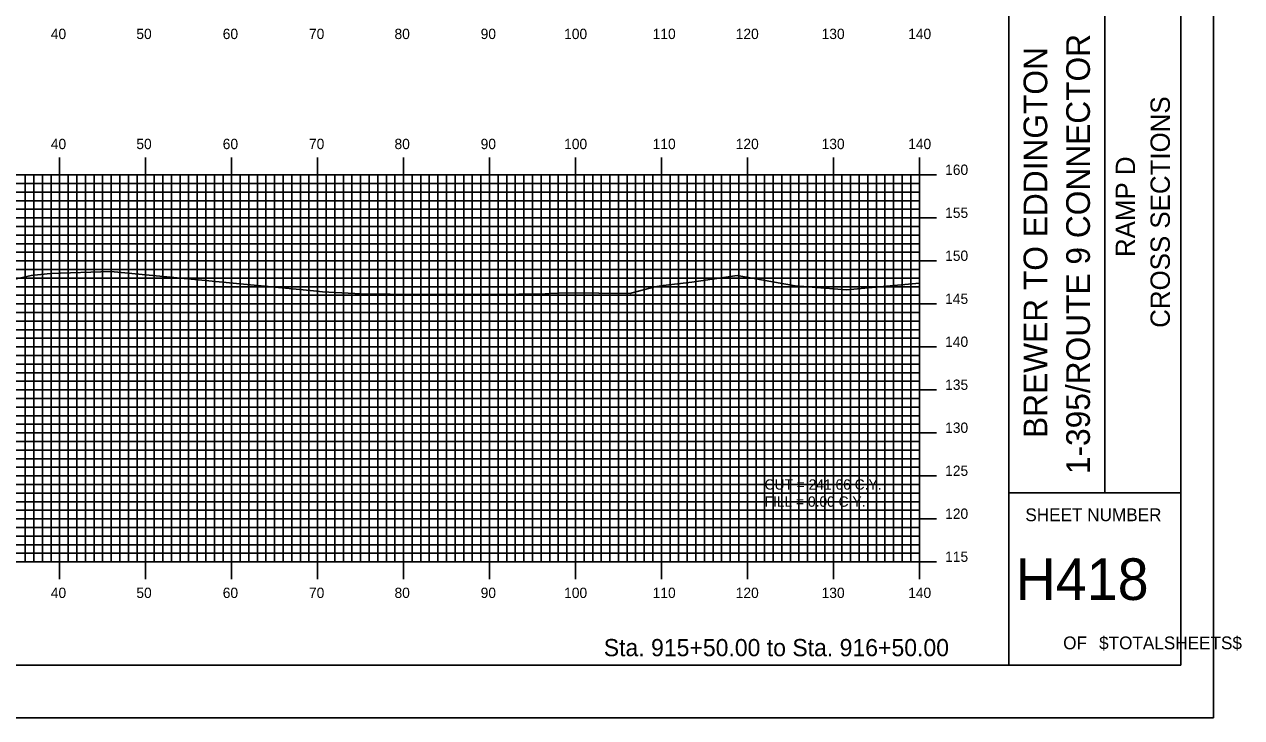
# Model space of a CAD drawing. Extents: x 861045 to 861388, y 364765 to 364985.
# Drawn here: x 861246.8 to 861388.4, y 364765.2 to 364845.8 of the extents above; entities that cross this region are included whole.
import ezdxf

# ---------------------------------------------------------------- set-up
doc = ezdxf.new("R2010")
doc.units = 0
for name, color, linetype in [('BORDER', 7, 'Continuous'), ('D_Text_Standard', 7, 'Continuous'), ('H_V ANNOTATION', 7, 'Continuous'), ('MAJOR', 7, 'Continuous'), ('MINOR', 7, 'Continuous'), ('PLOT BOUNDARY', 7, 'Continuous'), ('S_Roadway_Centerline', 7, 'Continuous')]:
    doc.layers.add(name, color=color, linetype=linetype)

msp = doc.modelspace()

# ---------------------------------------------------------------- linework, layer by layer
at = {"layer": 'BORDER'}
for p, q in [((861361.33, 364771.3), (861361.33, 364981.3)), ((861372.51, 364791.31), (861372.51, 364861.31)), ((861361.33, 364791.31), (861381.33, 364791.31))]:
    msp.add_line(p, q, dxfattribs=at)
msp.add_lwpolyline([(861061.33, 364771.3), (861381.33, 364771.3), (861381.33, 364981.3), (861061.33, 364981.3)], close=True, dxfattribs=at)
at = {"layer": 'MAJOR'}
for p, q in [((861250.93, 364830.31), (861250.93, 364828.3)), ((861260.93, 364830.31), (861260.93, 364828.3)), ((861270.93, 364830.31), (861270.93, 364828.3)), ((861280.93, 364830.31), (861280.93, 364828.3)), ((861290.93, 364830.31), (861290.93, 364828.3)), ((861300.93, 364830.31), (861300.93, 364828.3)), ((861310.93, 364830.31), (861310.93, 364828.3)), ((861320.93, 364830.31), (861320.93, 364828.3)), ((861330.93, 364830.31), (861330.93, 364828.3)), ((861340.93, 364830.31), (861340.93, 364828.3)), ((861350.93, 364830.31), (861350.93, 364828.3)), ((861070.93, 364828.3), (861350.93, 364828.3)), ((861070.93, 364828.3), (861350.93, 364828.3)), ((861250.93, 364783.3), (861250.93, 364828.3)), ((861260.93, 364783.3), (861260.93, 364828.3)), ((861270.93, 364783.3), (861270.93, 364828.3)), ((861280.93, 364783.3), (861280.93, 364828.3)), ((861290.93, 364783.3), (861290.93, 364828.3)), ((861300.93, 364783.3), (861300.93, 364828.3)), ((861310.93, 364783.3), (861310.93, 364828.3)), ((861320.93, 364783.3), (861320.93, 364828.3)), ((861330.93, 364783.3), (861330.93, 364828.3)), ((861340.93, 364783.3), (861340.93, 364828.3)), ((861352.93, 364828.3), (861348.92, 364828.3)), ((861350.93, 364783.3), (861350.93, 364828.3)), ((861350.93, 364783.3), (861350.93, 364828.3)), ((861070.93, 364823.3), (861350.93, 364823.3)), ((861352.93, 364823.3), (861348.92, 364823.3)), ((861070.93, 364818.3), (861350.93, 364818.3)), ((861352.93, 364818.3), (861348.92, 364818.3)), ((861070.93, 364813.3), (861350.93, 364813.3)), ((861352.93, 364813.3), (861348.92, 364813.3)), ((861070.93, 364808.3), (861350.93, 364808.3)), ((861352.93, 364808.3), (861348.92, 364808.3)), ((861070.93, 364803.3), (861350.93, 364803.3)), ((861352.93, 364803.3), (861348.92, 364803.3)), ((861070.93, 364798.3), (861350.93, 364798.3)), ((861352.93, 364798.3), (861348.92, 364798.3)), ((861070.93, 364793.3), (861350.93, 364793.3)), ((861352.93, 364793.3), (861348.92, 364793.3)), ((861070.93, 364788.3), (861350.93, 364788.3)), ((861352.93, 364788.3), (861348.92, 364788.3)), ((861070.93, 364783.3), (861350.93, 364783.3)), ((861070.93, 364783.3), (861350.93, 364783.3)), ((861250.93, 364781.3), (861250.93, 364783.3)), ((861260.93, 364781.3), (861260.93, 364783.3)), ((861270.93, 364781.3), (861270.93, 364783.3)), ((861280.93, 364781.3), (861280.93, 364783.3)), ((861290.93, 364781.3), (861290.93, 364783.3)), ((861300.93, 364781.3), (861300.93, 364783.3)), ((861310.93, 364781.3), (861310.93, 364783.3)), ((861320.93, 364781.3), (861320.93, 364783.3)), ((861330.93, 364781.3), (861330.93, 364783.3)), ((861340.93, 364781.3), (861340.93, 364783.3)), ((861352.93, 364783.3), (861348.92, 364783.3)), ((861350.93, 364781.3), (861350.93, 364783.3))]:
    msp.add_line(p, q, dxfattribs=at)
at = {"layer": 'MINOR'}
for p, q in [((861246.93, 364783.3), (861246.93, 364828.3)), ((861247.93, 364783.3), (861247.93, 364828.3)), ((861248.93, 364783.3), (861248.93, 364828.3)), ((861249.93, 364783.3), (861249.93, 364828.3)), ((861251.93, 364783.3), (861251.93, 364828.3)), ((861252.93, 364783.3), (861252.93, 364828.3)), ((861253.93, 364783.3), (861253.93, 364828.3)), ((861254.93, 364783.3), (861254.93, 364828.3)), ((861255.93, 364783.3), (861255.93, 364828.3)), ((861256.93, 364783.3), (861256.93, 364828.3)), ((861257.93, 364783.3), (861257.93, 364828.3)), ((861258.93, 364783.3), (861258.93, 364828.3)), ((861259.93, 364783.3), (861259.93, 364828.3)), ((861261.93, 364783.3), (861261.93, 364828.3)), ((861262.93, 364783.3), (861262.93, 364828.3)), ((861263.93, 364783.3), (861263.93, 364828.3)), ((861264.93, 364783.3), (861264.93, 364828.3)), ((861265.93, 364783.3), (861265.93, 364828.3)), ((861266.93, 364783.3), (861266.93, 364828.3)), ((861267.93, 364783.3), (861267.93, 364828.3)), ((861268.93, 364783.3), (861268.93, 364828.3)), ((861269.93, 364783.3), (861269.93, 364828.3)), ((861271.93, 364783.3), (861271.93, 364828.3)), ((861272.93, 364783.3), (861272.93, 364828.3)), ((861273.93, 364783.3), (861273.93, 364828.3)), ((861274.93, 364783.3), (861274.93, 364828.3)), ((861275.93, 364783.3), (861275.93, 364828.3)), ((861276.93, 364783.3), (861276.93, 364828.3)), ((861277.93, 364783.3), (861277.93, 364828.3)), ((861278.93, 364783.3), (861278.93, 364828.3)), ((861279.93, 364783.3), (861279.93, 364828.3)), ((861281.93, 364783.3), (861281.93, 364828.3)), ((861282.93, 364783.3), (861282.93, 364828.3)), ((861283.93, 364783.3), (861283.93, 364828.3)), ((861284.93, 364783.3), (861284.93, 364828.3)), ((861285.93, 364783.3), (861285.93, 364828.3)), ((861286.93, 364783.3), (861286.93, 364828.3)), ((861287.93, 364783.3), (861287.93, 364828.3)), ((861288.93, 364783.3), (861288.93, 364828.3)), ((861289.93, 364783.3), (861289.93, 364828.3)), ((861291.93, 364783.3), (861291.93, 364828.3)), ((861292.93, 364783.3), (861292.93, 364828.3)), ((861293.93, 364783.3), (861293.93, 364828.3)), ((861294.93, 364783.3), (861294.93, 364828.3)), ((861295.93, 364783.3), (861295.93, 364828.3)), ((861296.93, 364783.3), (861296.93, 364828.3)), ((861297.93, 364783.3), (861297.93, 364828.3)), ((861298.93, 364783.3), (861298.93, 364828.3)), ((861299.93, 364783.3), (861299.93, 364828.3)), ((861301.93, 364783.3), (861301.93, 364828.3)), ((861302.93, 364783.3), (861302.93, 364828.3)), ((861303.93, 364783.3), (861303.93, 364828.3)), ((861304.93, 364783.3), (861304.93, 364828.3)), ((861305.93, 364783.3), (861305.93, 364828.3)), ((861306.93, 364783.3), (861306.93, 364828.3)), ((861307.93, 364783.3), (861307.93, 364828.3)), ((861308.93, 364783.3), (861308.93, 364828.3)), ((861309.93, 364783.3), (861309.93, 364828.3)), ((861311.93, 364783.3), (861311.93, 364828.3)), ((861312.93, 364783.3), (861312.93, 364828.3)), ((861313.93, 364783.3), (861313.93, 364828.3)), ((861314.93, 364783.3), (861314.93, 364828.3)), ((861315.93, 364783.3), (861315.93, 364828.3)), ((861316.93, 364783.3), (861316.93, 364828.3)), ((861317.93, 364783.3), (861317.93, 364828.3)), ((861318.93, 364783.3), (861318.93, 364828.3)), ((861319.93, 364783.3), (861319.93, 364828.3)), ((861321.93, 364783.3), (861321.93, 364828.3)), ((861322.93, 364783.3), (861322.93, 364828.3)), ((861323.93, 364783.3), (861323.93, 364828.3)), ((861324.93, 364783.3), (861324.93, 364828.3)), ((861325.93, 364783.3), (861325.93, 364828.3)), ((861326.93, 364783.3), (861326.93, 364828.3)), ((861327.93, 364783.3), (861327.93, 364828.3)), ((861328.93, 364783.3), (861328.93, 364828.3)), ((861329.93, 364783.3), (861329.93, 364828.3)), ((861331.93, 364783.3), (861331.93, 364828.3)), ((861332.93, 364783.3), (861332.93, 364828.3)), ((861333.93, 364783.3), (861333.93, 364828.3)), ((861334.93, 364783.3), (861334.93, 364828.3)), ((861335.93, 364783.3), (861335.93, 364828.3)), ((861336.93, 364783.3), (861336.93, 364828.3)), ((861337.93, 364783.3), (861337.93, 364828.3)), ((861338.93, 364783.3), (861338.93, 364828.3)), ((861339.93, 364783.3), (861339.93, 364828.3)), ((861341.93, 364783.3), (861341.93, 364828.3)), ((861342.93, 364783.3), (861342.93, 364828.3)), ((861343.93, 364783.3), (861343.93, 364828.3)), ((861344.93, 364783.3), (861344.93, 364828.3)), ((861345.93, 364783.3), (861345.93, 364828.3)), ((861346.93, 364783.3), (861346.93, 364828.3)), ((861347.93, 364783.3), (861347.93, 364828.3)), ((861348.93, 364783.3), (861348.93, 364828.3)), ((861349.93, 364783.3), (861349.93, 364828.3)), ((861070.93, 364827.3), (861350.93, 364827.3)), ((861350.93, 364827.3), (861348.92, 364827.3)), ((861070.93, 364826.3), (861350.93, 364826.3)), ((861350.93, 364826.3), (861348.92, 364826.3)), ((861070.93, 364825.3), (861350.93, 364825.3)), ((861070.93, 364824.3), (861350.93, 364824.3)), ((861350.93, 364825.3), (861348.92, 364825.3)), ((861350.93, 364824.3), (861348.92, 364824.3)), ((861070.93, 364822.3), (861350.93, 364822.3)), ((861070.93, 364821.3), (861350.93, 364821.3)), ((861350.93, 364822.3), (861348.92, 364822.3)), ((861350.93, 364821.3), (861348.92, 364821.3)), ((861070.93, 364820.3), (861350.93, 364820.3)), ((861350.93, 364820.3), (861348.92, 364820.3)), ((861070.93, 364819.3), (861350.93, 364819.3)), ((861350.93, 364819.3), (861348.92, 364819.3)), ((861070.93, 364817.3), (861350.93, 364817.3)), ((861350.93, 364817.3), (861348.92, 364817.3)), ((861070.93, 364816.3), (861350.93, 364816.3)), ((861350.93, 364816.3), (861348.92, 364816.3)), ((861070.93, 364815.3), (861350.93, 364815.3)), ((861070.93, 364814.3), (861350.93, 364814.3)), ((861350.93, 364815.3), (861348.92, 364815.3)), ((861350.93, 364814.3), (861348.92, 364814.3)), ((861070.93, 364812.3), (861350.93, 364812.3)), ((861070.93, 364811.3), (861350.93, 364811.3)), ((861350.93, 364812.3), (861348.92, 364812.3)), ((861350.93, 364811.3), (861348.92, 364811.3)), ((861070.93, 364810.3), (861350.93, 364810.3)), ((861350.93, 364810.3), (861348.92, 364810.3)), ((861070.93, 364809.3), (861350.93, 364809.3)), ((861350.93, 364809.3), (861348.92, 364809.3)), ((861070.93, 364807.3), (861350.93, 364807.3)), ((861350.93, 364807.3), (861348.92, 364807.3)), ((861070.93, 364806.3), (861350.93, 364806.3)), ((861350.93, 364806.3), (861348.92, 364806.3)), ((861070.93, 364805.3), (861350.93, 364805.3)), ((861070.93, 364804.3), (861350.93, 364804.3)), ((861350.93, 364805.3), (861348.92, 364805.3)), ((861350.93, 364804.3), (861348.92, 364804.3)), ((861070.93, 364802.3), (861350.93, 364802.3)), ((861070.93, 364801.3), (861350.93, 364801.3)), ((861350.93, 364802.3), (861348.92, 364802.3)), ((861350.93, 364801.3), (861348.92, 364801.3)), ((861070.93, 364800.3), (861350.93, 364800.3)), ((861350.93, 364800.3), (861348.92, 364800.3)), ((861070.93, 364799.3), (861350.93, 364799.3)), ((861350.93, 364799.3), (861348.92, 364799.3)), ((861070.93, 364797.3), (861350.93, 364797.3)), ((861350.93, 364797.3), (861348.92, 364797.3)), ((861070.93, 364796.3), (861350.93, 364796.3)), ((861350.93, 364796.3), (861348.92, 364796.3)), ((861070.93, 364795.3), (861350.93, 364795.3)), ((861070.93, 364794.3), (861350.93, 364794.3)), ((861350.93, 364795.3), (861348.92, 364795.3)), ((861350.93, 364794.3), (861348.92, 364794.3)), ((861070.93, 364792.3), (861350.93, 364792.3)), ((861350.93, 364792.3), (861348.92, 364792.3)), ((861070.93, 364791.3), (861350.93, 364791.3)), ((861070.93, 364790.3), (861350.93, 364790.3)), ((861350.93, 364791.3), (861348.92, 364791.3)), ((861350.93, 364790.3), (861348.92, 364790.3)), ((861070.93, 364789.3), (861350.93, 364789.3)), ((861350.93, 364789.3), (861348.92, 364789.3)), ((861070.93, 364787.3), (861350.93, 364787.3)), ((861350.93, 364787.3), (861348.92, 364787.3)), ((861070.93, 364786.3), (861350.93, 364786.3)), ((861350.93, 364786.3), (861348.92, 364786.3)), ((861070.93, 364785.3), (861350.93, 364785.3)), ((861070.93, 364784.3), (861350.93, 364784.3)), ((861350.93, 364785.3), (861348.92, 364785.3)), ((861350.93, 364784.3), (861348.92, 364784.3))]:
    msp.add_line(p, q, dxfattribs=at)
at = {"layer": 'PLOT BOUNDARY'}
msp.add_lwpolyline([(861045.14, 364765.18), (861385.14, 364765.18), (861385.14, 364985.18), (861045.14, 364985.18)], close=True, dxfattribs=at)
at = {"layer": 'S_Roadway_Centerline'}
msp.add_lwpolyline([(861244.71, 364815.93), (861247.63, 364816.62), (861249.88, 364816.84), (861256.88, 364817.06), (861280.45, 364814.83), (861281.49, 364814.7), (861286.02, 364814.46), (861289.15, 364814.44), (861289.29, 364814.44), (861289.33, 364814.44), (861289.38, 364814.44), (861301.25, 364814.38), (861307.41, 364814.48), (861307.92, 364814.49), (861310.01, 364814.57), (861317.29, 364814.51), (861317.52, 364814.59), (861320.18, 364815.3), (861321.14, 364815.45), (861324.48, 364815.84), (861329.73, 364816.62), (861336.49, 364815.41), (861342.45, 364814.94), (861350.93, 364815.72)], dxfattribs=at)

# ---------------------------------------------------------------- texts
at = {"layer": 'BORDER'}
for s, height, p in [('1-395/ROUTE 9 CONNECTOR', 2.7557, (861370.77, 364793.5)), ('BREWER TO EDDINGTON', 2.7557, (861365.81, 364797.71)), ('CROSS SECTIONS', 2.25, (861380.07, 364810.52)), ('RAMP D', 2.25, (861376.02, 364818.75))]:
    msp.add_text(s, height=height, rotation=90, dxfattribs=at).set_placement(p)
for s, height, p in [('SHEET NUMBER', 1.4905, (861363.26, 364788.03)), ('H418', 4.839, (861362.13, 364778.87)), ('OF', 1.491, (861367.66, 364773.13)), ('$TOTALSHEETS$', 1.4905, (861371.84, 364773.13))]:
    msp.add_text(s, height=height, dxfattribs=at).set_placement(p)
at = {"layer": 'D_Text_Standard'}
for s, p in [('CUT = 241.66 C.Y.', (861332.93, 364791.7)), ('FILL = 0.00 C.Y.', (861332.93, 364789.71))]:
    msp.add_text(s, height=1.2, dxfattribs=at).set_placement(p)
at = {"layer": 'H_V ANNOTATION'}
for s, height, p in [('40', 1.2, (861249.9, 364844.1)), ('50', 1.2, (861259.85, 364844.1)), ('60', 1.2, (861269.9, 364844.1)), ('70', 1.2, (861279.93, 364844.1)), ('80', 1.2, (861289.88, 364844.1)), ('90', 1.2, (861299.9, 364844.1)), ('100', 1.2, (861309.61, 364844.1)), ('110', 1.2, (861319.91, 364844.1)), ('120', 1.2, (861329.57, 364844.1)), ('130', 1.2, (861339.56, 364844.1)), ('140', 1.2, (861349.63, 364844.1)), ('40', 1.2, (861249.9, 364831.3)), ('50', 1.2, (861259.85, 364831.3)), ('60', 1.2, (861269.9, 364831.3)), ('70', 1.2, (861279.93, 364831.3)), ('80', 1.2, (861289.88, 364831.3)), ('90', 1.2, (861299.9, 364831.3)), ('100', 1.2, (861309.61, 364831.3)), ('110', 1.2, (861319.91, 364831.3)), ('120', 1.2, (861329.57, 364831.3)), ('130', 1.2, (861339.56, 364831.3)), ('140', 1.2, (861349.63, 364831.3)), ('160', 1.2, (861353.93, 364828.3)), ('155', 1.2, (861353.93, 364823.3)), ('150', 1.2, (861353.93, 364818.3)), ('145', 1.2, (861353.93, 364813.3)), ('140', 1.2, (861353.93, 364808.3)), ('135', 1.2, (861353.93, 364803.3)), ('130', 1.2, (861353.93, 364798.3)), ('125', 1.2, (861353.93, 364793.3)), ('120', 1.2, (861353.93, 364788.3)), ('115', 1.2, (861353.93, 364783.3)), ('40', 1.2, (861249.9, 364779.1)), ('50', 1.2, (861259.85, 364779.1)), ('60', 1.2, (861269.9, 364779.1)), ('70', 1.2, (861279.93, 364779.1)), ('80', 1.2, (861289.88, 364779.1)), ('90', 1.2, (861299.9, 364779.1)), ('100', 1.2, (861309.61, 364779.1)), ('110', 1.2, (861319.91, 364779.1)), ('120', 1.2, (861329.57, 364779.1)), ('130', 1.2, (861339.56, 364779.1)), ('140', 1.2, (861349.63, 364779.1)), ('Sta. 915+50.00 to Sta. 916+50.00', 2.0004, (861314.22, 364772.33))]:
    msp.add_text(s, height=height, dxfattribs=at).set_placement(p)

doc.saveas('drawing.dxf')
